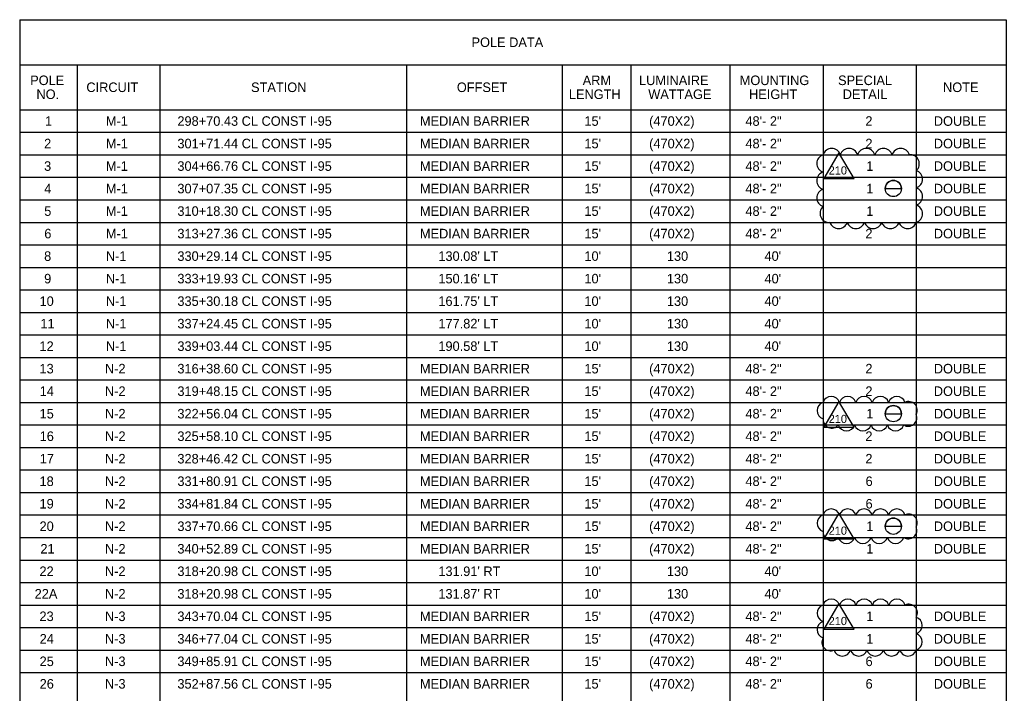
# Model space of a CAD drawing. Extents: x -816.7 to -727.6, y -2197.9 to -2187.8.
# Drawn here: x -815.95 to -808.72, y -2193.03 to -2188.1 of the extents above; entities that cross this region are included whole.
import ezdxf

# ---------------------------------------------------------------- set-up
doc = ezdxf.new("R2010")
doc.units = 0
for name, color, linetype in [('ClipBorder_dp', 7, 'Continuous'), ('MatchLines_dp', 7, 'Continuous'), ('NorthArw_dp', 7, 'Continuous'), ('PlotBorder_dp', 7, 'Continuous'), ('Scale_dp', 7, 'Continuous')]:
    doc.layers.add(name, color=color, linetype=linetype)

msp = doc.modelspace()

# ---------------------------------------------------------------- linework, layer by layer
at = {"layer": 'ClipBorder_dp'}
for p, q in [((-809.6078, -2189.3348), (-809.4893, -2189.3348)), ((-809.6078, -2189.3348), (-809.4893, -2189.3348)), ((-809.6078, -2190.9848), (-809.4893, -2190.9848)), ((-809.6078, -2190.9848), (-809.4893, -2190.9848)), ((-809.6078, -2191.8098), (-809.4893, -2191.8098)), ((-809.6078, -2191.8098), (-809.4893, -2191.8098))]:
    msp.add_line(p, q, dxfattribs=at)
for centre in [(-809.5485, -2189.3348), (-809.5485, -2190.9848), (-809.5485, -2191.8098)]:
    msp.add_circle(centre, 0.0593, dxfattribs=at)
for centre in [(-809.5485, -2189.3348), (-809.5485, -2190.9848), (-809.5485, -2191.8098)]:
    msp.add_arc(centre, 0.0593, 0, 180, dxfattribs=at)
at = {"layer": 'MatchLines_dp'}
for p, q in [((-815.9511, -2188.7573), (-808.7211, -2188.7573)), ((-815.9511, -2188.9223), (-808.7211, -2188.9223)), ((-815.9511, -2188.9223), (-808.7211, -2188.9223)), ((-815.9511, -2189.0873), (-808.7211, -2189.0873)), ((-815.9511, -2189.0873), (-808.7211, -2189.0873)), ((-815.9511, -2189.2523), (-808.7211, -2189.2523)), ((-815.9511, -2189.2523), (-808.7211, -2189.2523)), ((-815.9511, -2189.4173), (-808.7211, -2189.4173)), ((-815.9511, -2189.4173), (-808.7211, -2189.4173)), ((-815.9511, -2189.5823), (-808.7211, -2189.5823)), ((-815.9511, -2189.5823), (-808.7211, -2189.5823)), ((-815.9511, -2189.7473), (-808.7211, -2189.7473)), ((-815.9511, -2189.7473), (-808.7211, -2189.7473)), ((-815.9511, -2189.9123), (-808.7211, -2189.9123)), ((-815.9511, -2189.9123), (-808.7211, -2189.9123)), ((-815.9511, -2190.0773), (-808.7211, -2190.0773)), ((-815.9511, -2190.0773), (-808.7211, -2190.0773)), ((-815.9511, -2190.2423), (-808.7211, -2190.2423)), ((-815.9511, -2190.2423), (-808.7211, -2190.2423)), ((-815.9511, -2190.4073), (-808.7211, -2190.4073)), ((-815.9511, -2190.4073), (-808.7211, -2190.4073)), ((-815.9511, -2190.5723), (-808.7211, -2190.5723)), ((-815.9511, -2190.5723), (-808.7211, -2190.5723)), ((-815.9511, -2190.7373), (-808.7211, -2190.7373)), ((-815.9511, -2190.7373), (-808.7211, -2190.7373)), ((-815.9511, -2190.9023), (-808.7211, -2190.9023)), ((-815.9511, -2190.9023), (-808.7211, -2190.9023)), ((-815.9511, -2191.0673), (-808.7211, -2191.0673)), ((-815.9511, -2191.0673), (-808.7211, -2191.0673)), ((-815.9511, -2191.2323), (-808.7211, -2191.2323)), ((-815.9511, -2191.2323), (-808.7211, -2191.2323)), ((-815.9511, -2191.3973), (-808.7211, -2191.3973)), ((-815.9511, -2191.3973), (-808.7211, -2191.3973)), ((-815.9511, -2191.5623), (-808.7211, -2191.5623)), ((-815.9511, -2191.5623), (-808.7211, -2191.5623)), ((-815.9511, -2191.7273), (-808.7211, -2191.7273)), ((-815.9511, -2191.7273), (-808.7211, -2191.7273)), ((-815.9511, -2191.8923), (-808.7211, -2191.8923)), ((-815.9511, -2191.8923), (-808.7211, -2191.8923)), ((-815.9511, -2192.0573), (-808.7211, -2192.0573)), ((-815.9511, -2192.0573), (-808.7211, -2192.0573)), ((-815.9511, -2192.2223), (-808.7211, -2192.2223)), ((-815.9511, -2192.2223), (-808.7211, -2192.2223)), ((-815.9511, -2192.3873), (-808.7211, -2192.3873)), ((-815.9511, -2192.3873), (-808.7211, -2192.3873)), ((-815.9511, -2192.5523), (-808.7211, -2192.5523)), ((-815.9511, -2192.5523), (-808.7211, -2192.5523)), ((-815.9511, -2192.7173), (-808.7211, -2192.7173)), ((-815.9511, -2192.7173), (-808.7211, -2192.7173)), ((-815.9511, -2192.8823), (-808.7211, -2192.8823)), ((-815.9511, -2192.8823), (-808.7211, -2192.8823))]:
    msp.add_line(p, q, dxfattribs=at)
at = {"layer": 'NorthArw_dp'}
for p, q in [((-815.9511, -2188.0973), (-808.7211, -2188.0973)), ((-815.9511, -2188.0973), (-815.9511, -2194.6973)), ((-808.7211, -2188.0973), (-808.7211, -2194.6973)), ((-808.7211, -2188.0973), (-808.7211, -2194.6973)), ((-815.9511, -2188.4273), (-808.7211, -2188.4273)), ((-815.9511, -2188.4273), (-808.7211, -2188.4273))]:
    msp.add_line(p, q, dxfattribs=at)
at = {"layer": 'PlotBorder_dp'}
for points in [[(-809.9493, -2189.0739), (-810.057, -2189.2619), (-809.8364, -2189.2619)], [(-809.9493, -2190.8953), (-810.057, -2191.0833), (-809.8364, -2191.0833)], [(-809.9493, -2191.7141), (-810.057, -2191.9022), (-809.8364, -2191.9022)], [(-809.9493, -2192.3765), (-810.057, -2192.5645), (-809.8364, -2192.5645)]]:
    msp.add_lwpolyline(points, close=True, dxfattribs=at)
for centre, radius, start, end in [((-810.0436, -2189.1505), 0.0663, 107.5, 252.5), ((-810.0004, -2189.1072), 0.0663, 17.5, 162.5), ((-809.874, -2189.1072), 0.0663, 17.5, 162.5), ((-809.7475, -2189.1072), 0.0663, 17.5, 162.5), ((-809.6211, -2189.1072), 0.0663, 17.5, 162.5), ((-809.4947, -2189.1072), 0.0663, 17.5, 162.5), ((-809.4245, -2189.1531), 0.0662, 311.04336, 96.04336), ((-810.0436, -2189.2769), 0.0663, 107.5, 252.5), ((-809.401, -2189.2662), 0.0663, 287.5, 72.5), ((-810.0436, -2189.4033), 0.0663, 107.5, 252.5), ((-809.401, -2189.3926), 0.0663, 287.5, 72.5), ((-809.401, -2189.5191), 0.0663, 287.5, 72.5), ((-810.0201, -2189.5164), 0.0662, 131.04336, 276.04336), ((-809.9499, -2189.5623), 0.0663, 197.5, 342.5), ((-809.8235, -2189.5623), 0.0663, 197.5, 342.5), ((-809.6971, -2189.5623), 0.0663, 197.5, 342.5), ((-809.5707, -2189.5623), 0.0663, 197.5, 342.5), ((-809.4443, -2189.5623), 0.0663, 197.5, 342.5), ((-810.0447, -2190.9623), 0.0629, 107.5, 252.5), ((-810.0036, -2190.9212), 0.0629, 17.5, 162.5), ((-809.8835, -2190.9212), 0.0629, 17.5, 162.5), ((-809.7635, -2190.9212), 0.0629, 17.5, 162.5), ((-809.6435, -2190.9212), 0.0629, 17.5, 162.5), ((-809.5234, -2190.9212), 0.0629, 17.5, 162.5), ((-809.436, -2190.9588), 0.0629, 330.87934, 115.87934), ((-810.0009, -2191.0272), 0.0629, 175.48211, 320.48211), ((-809.4389, -2191.014), 0.0629, 237.99061, 22.99061), ((-809.8924, -2191.0483), 0.0629, 197.5, 342.5), ((-809.7723, -2191.0483), 0.0629, 197.5, 342.5), ((-809.6523, -2191.0483), 0.0629, 197.5, 342.5), ((-809.5323, -2191.0483), 0.0629, 197.5, 342.5), ((-810.0036, -2191.7462), 0.0629, 17.5, 162.5), ((-809.8835, -2191.7462), 0.0629, 17.5, 162.5), ((-809.7635, -2191.7462), 0.0629, 17.5, 162.5), ((-809.6435, -2191.7462), 0.0629, 17.5, 162.5), ((-809.5234, -2191.7462), 0.0629, 17.5, 162.5), ((-810.0447, -2191.7873), 0.0629, 107.5, 252.5), ((-809.436, -2191.7838), 0.0629, 330.87934, 115.87934), ((-809.4389, -2191.839), 0.0629, 237.99061, 22.99061), ((-810.0009, -2191.8522), 0.0629, 175.48211, 320.48211), ((-809.8924, -2191.8733), 0.0629, 197.5, 342.5), ((-809.7723, -2191.8733), 0.0629, 197.5, 342.5), ((-809.6523, -2191.8733), 0.0629, 197.5, 342.5), ((-809.5323, -2191.8733), 0.0629, 197.5, 342.5), ((-810.0034, -2192.4062), 0.0631, 17.5, 162.5), ((-809.883, -2192.4062), 0.0631, 17.5, 162.5), ((-809.7627, -2192.4062), 0.0631, 17.5, 162.5), ((-809.6423, -2192.4062), 0.0631, 17.5, 162.5), ((-809.5219, -2192.4062), 0.0631, 17.5, 162.5), ((-810.0446, -2192.4474), 0.0631, 107.5, 252.5), ((-809.4355, -2192.4446), 0.0631, 329.60153, 114.60153), ((-809.4001, -2192.5367), 0.0631, 287.5, 72.5), ((-810.0446, -2192.5678), 0.0631, 107.5, 252.5), ((-810.0092, -2192.6599), 0.0631, 149.60153, 294.60153), ((-809.4001, -2192.6571), 0.0631, 287.5, 72.5), ((-809.9227, -2192.6983), 0.0631, 197.5, 342.5), ((-809.8024, -2192.6983), 0.0631, 197.5, 342.5), ((-809.682, -2192.6983), 0.0631, 197.5, 342.5), ((-809.5616, -2192.6983), 0.0631, 197.5, 342.5), ((-809.4413, -2192.6983), 0.0631, 197.5, 342.5)]:
    msp.add_arc(centre, radius, start, end, dxfattribs=at)
at = {"layer": 'Scale_dp'}
for p, q in [((-815.5311, -2188.4273), (-815.5311, -2194.6973)), ((-815.5311, -2188.4273), (-815.5311, -2194.6973)), ((-814.9236, -2188.4273), (-814.9236, -2194.6973)), ((-814.9236, -2188.4273), (-814.9236, -2194.6973)), ((-813.1161, -2188.4273), (-813.1161, -2194.6973)), ((-813.1161, -2188.4273), (-813.1161, -2194.6973)), ((-811.9761, -2188.4273), (-811.9761, -2194.6973)), ((-811.9761, -2188.4273), (-811.9761, -2194.6973)), ((-811.4736, -2188.4273), (-811.4736, -2194.6973)), ((-811.4736, -2188.4273), (-811.4736, -2194.6973)), ((-810.7461, -2188.4273), (-810.7461, -2194.6973)), ((-810.7461, -2188.4273), (-810.7461, -2194.6973)), ((-810.0636, -2188.4273), (-810.0636, -2194.6973)), ((-810.0636, -2188.4273), (-810.0636, -2194.6973)), ((-809.3811, -2188.4273), (-809.3811, -2194.6973)), ((-815.9511, -2188.7573), (-808.7211, -2188.7573))]:
    msp.add_line(p, q, dxfattribs=at)

# ---------------------------------------------------------------- texts
at = {"layer": 'ClipBorder_dp'}
for s, p in [('POLE DATA', (-812.64, -2188.2973)), ('POLE', (-815.8744, -2188.5763)), ('ARM', (-811.8253, -2188.5763)), ('LUMINAIRE', (-811.4125, -2188.5763)), ('MOUNTING', (-810.6745, -2188.5763)), ('SPECIAL', (-809.9537, -2188.5763)), ('CIRCUIT', (-815.4627, -2188.6273)), ('STATION', (-814.2557, -2188.6273)), ('OFFSET', (-812.7476, -2188.6273)), ('NOTE', (-809.1844, -2188.6273)), ('NO.', (-815.8287, -2188.6783)), ('LENGTH', (-811.9268, -2188.6783)), ('WATTAGE', (-811.3447, -2188.6783)), ('HEIGHT', (-810.6063, -2188.6783)), ('DETAIL', (-809.9199, -2188.6783)), ('1', (-815.7658, -2188.8748)), ('M-1', (-815.3198, -2188.8748)), ('298+70.43 CL CONST I-95', (-814.7957, -2188.8748)), ('MEDIAN BARRIER', (-813.0182, -2188.8748)), ("15'", (-811.8128, -2188.8748)), ('(470X2)', (-811.3383, -2188.8748)), ('48\'- 2"', (-810.6327, -2188.8748)), ('2', (-809.7537, -2188.8748)), ('DOUBLE', (-809.2521, -2188.8748)), ('2', (-815.7725, -2189.0398)), ('M-1', (-815.3198, -2189.0398)), ('301+71.44 CL CONST I-95', (-814.7957, -2189.0398)), ('MEDIAN BARRIER', (-813.0182, -2189.0398)), ("15'", (-811.8128, -2189.0398)), ('(470X2)', (-811.3383, -2189.0398)), ('48\'- 2"', (-810.6327, -2189.0398)), ('2', (-809.7537, -2189.0398)), ('DOUBLE', (-809.2521, -2189.0398)), ('3', (-815.7725, -2189.2048)), ('M-1', (-815.3198, -2189.2048)), ('304+66.76 CL CONST I-95', (-814.7957, -2189.2048)), ('MEDIAN BARRIER', (-813.0182, -2189.2048)), ("15'", (-811.8128, -2189.2048)), ('(470X2)', (-811.3383, -2189.2048)), ('48\'- 2"', (-810.6327, -2189.2048)), ('1', (-809.747, -2189.2048)), ('DOUBLE', (-809.2521, -2189.2048)), ('4', (-815.7711, -2189.3698)), ('M-1', (-815.3198, -2189.3698)), ('307+07.35 CL CONST I-95', (-814.7957, -2189.3698)), ('MEDIAN BARRIER', (-813.0182, -2189.3698)), ("15'", (-811.8128, -2189.3698)), ('(470X2)', (-811.3383, -2189.3698)), ('48\'- 2"', (-810.6327, -2189.3698)), ('1', (-809.747, -2189.3698)), ('DOUBLE', (-809.2521, -2189.3698)), ('5', (-815.7716, -2189.5348)), ('M-1', (-815.3198, -2189.5348)), ('310+18.30 CL CONST I-95', (-814.7957, -2189.5348)), ('MEDIAN BARRIER', (-813.0182, -2189.5348)), ("15'", (-811.8128, -2189.5348)), ('(470X2)', (-811.3383, -2189.5348)), ('48\'- 2"', (-810.6327, -2189.5348)), ('1', (-809.747, -2189.5348)), ('DOUBLE', (-809.2521, -2189.5348)), ('6', (-815.7711, -2189.6998)), ('M-1', (-815.3198, -2189.6998)), ('313+27.36 CL CONST I-95', (-814.7957, -2189.6998)), ('MEDIAN BARRIER', (-813.0182, -2189.6998)), ("15'", (-811.8128, -2189.6998)), ('(470X2)', (-811.3383, -2189.6998)), ('48\'- 2"', (-810.6327, -2189.6998)), ('2', (-809.7537, -2189.6998)), ('DOUBLE', (-809.2521, -2189.6998)), ('8', (-815.7722, -2189.8648)), ('N-1', (-815.3198, -2189.8648)), ('330+29.14 CL CONST I-95', (-814.7957, -2189.8648)), ("130.08' LT", (-812.8831, -2189.8648)), ("10'", (-811.8128, -2189.8648)), ('130', (-811.2084, -2189.8648)), ("40'", (-810.4928, -2189.8648)), ('9', (-815.7721, -2190.0298)), ('N-1', (-815.3198, -2190.0298)), ('333+19.93 CL CONST I-95', (-814.7957, -2190.0298)), ("150.16' LT", (-812.8831, -2190.0298)), ("10'", (-811.8128, -2190.0298)), ('130', (-811.2084, -2190.0298)), ("40'", (-810.4928, -2190.0298)), ('10', (-815.8058, -2190.1948)), ('N-1', (-815.3198, -2190.1948)), ('335+30.18 CL CONST I-95', (-814.7957, -2190.1948)), ("161.75' LT", (-812.8831, -2190.1948)), ("10'", (-811.8128, -2190.1948)), ('130', (-811.2084, -2190.1948)), ("40'", (-810.4928, -2190.1948)), ('11', (-815.7996, -2190.3598)), ('N-1', (-815.3198, -2190.3598)), ('337+24.45 CL CONST I-95', (-814.7957, -2190.3598)), ("177.82' LT", (-812.8831, -2190.3598)), ("10'", (-811.8128, -2190.3598)), ('130', (-811.2084, -2190.3598)), ("40'", (-810.4928, -2190.3598)), ('12', (-815.8064, -2190.5248)), ('N-1', (-815.3198, -2190.5248)), ('339+03.44 CL CONST I-95', (-814.7957, -2190.5248)), ("190.58' LT", (-812.8831, -2190.5248)), ("10'", (-811.8128, -2190.5248)), ('130', (-811.2084, -2190.5248)), ("40'", (-810.4928, -2190.5248)), ('(470X2)', (-811.3383, -2190.6898)), ('13', (-815.8064, -2190.6898)), ('N-2', (-815.3265, -2190.6898)), ('316+38.60 CL CONST I-95', (-814.7957, -2190.6898)), ('MEDIAN BARRIER', (-813.0182, -2190.6898)), ("15'", (-811.8128, -2190.6898)), ('48\'- 2"', (-810.6327, -2190.6898)), ('2', (-809.7537, -2190.6898)), ('DOUBLE', (-809.2521, -2190.6898)), ('14', (-815.805, -2190.8548)), ('N-2', (-815.3265, -2190.8548)), ('319+48.15 CL CONST I-95', (-814.7957, -2190.8548)), ('MEDIAN BARRIER', (-813.0182, -2190.8548)), ("15'", (-811.8128, -2190.8548)), ('(470X2)', (-811.3383, -2190.8548)), ('48\'- 2"', (-810.6327, -2190.8548)), ('2', (-809.7537, -2190.8548)), ('DOUBLE', (-809.2521, -2190.8548)), ('15', (-815.8055, -2191.0198)), ('N-2', (-815.3265, -2191.0198)), ('322+56.04 CL CONST I-95', (-814.7957, -2191.0198)), ('MEDIAN BARRIER', (-813.0182, -2191.0198)), ("15'", (-811.8128, -2191.0198)), ('(470X2)', (-811.3383, -2191.0198)), ('48\'- 2"', (-810.6327, -2191.0198)), ('1', (-809.747, -2191.0198)), ('DOUBLE', (-809.2521, -2191.0198)), ('16', (-815.805, -2191.1848)), ('N-2', (-815.3265, -2191.1848)), ('325+58.10 CL CONST I-95', (-814.7957, -2191.1848)), ('MEDIAN BARRIER', (-813.0182, -2191.1848)), ("15'", (-811.8128, -2191.1848)), ('(470X2)', (-811.3383, -2191.1848)), ('48\'- 2"', (-810.6327, -2191.1848)), ('2', (-809.7537, -2191.1848)), ('DOUBLE', (-809.2521, -2191.1848)), ('17', (-815.8044, -2191.3498)), ('N-2', (-815.3265, -2191.3498)), ('328+46.42 CL CONST I-95', (-814.7957, -2191.3498)), ('MEDIAN BARRIER', (-813.0182, -2191.3498)), ("15'", (-811.8128, -2191.3498)), ('(470X2)', (-811.3383, -2191.3498)), ('48\'- 2"', (-810.6327, -2191.3498)), ('2', (-809.7537, -2191.3498)), ('DOUBLE', (-809.2521, -2191.3498)), ('18', (-815.8061, -2191.5148)), ('N-2', (-815.3265, -2191.5148)), ('331+80.91 CL CONST I-95', (-814.7957, -2191.5148)), ('MEDIAN BARRIER', (-813.0182, -2191.5148)), ("15'", (-811.8128, -2191.5148)), ('(470X2)', (-811.3383, -2191.5148)), ('48\'- 2"', (-810.6327, -2191.5148)), ('6', (-809.7523, -2191.5148)), ('DOUBLE', (-809.2521, -2191.5148)), ('19', (-815.806, -2191.6798)), ('N-2', (-815.3265, -2191.6798)), ('334+81.84 CL CONST I-95', (-814.7957, -2191.6798)), ('MEDIAN BARRIER', (-813.0182, -2191.6798)), ("15'", (-811.8128, -2191.6798)), ('(470X2)', (-811.3383, -2191.6798)), ('48\'- 2"', (-810.6327, -2191.6798)), ('6', (-809.7523, -2191.6798)), ('DOUBLE', (-809.2521, -2191.6798)), ('20', (-815.8058, -2191.8448)), ('N-2', (-815.3265, -2191.8448)), ('337+70.66 CL CONST I-95', (-814.7957, -2191.8448)), ('(470X2)', (-811.3383, -2191.8448)), ('48\'- 2"', (-810.6327, -2191.8448)), ('DOUBLE', (-809.2521, -2191.8448)), ('MEDIAN BARRIER', (-813.0182, -2191.8448)), ("15'", (-811.8128, -2191.8448)), ('1', (-809.747, -2191.8448)), ('21', (-815.7996, -2192.0098)), ('N-2', (-815.3265, -2192.0098)), ('340+52.89 CL CONST I-95', (-814.7957, -2192.0098)), ('MEDIAN BARRIER', (-813.0182, -2192.0098)), ("15'", (-811.8128, -2192.0098)), ('(470X2)', (-811.3383, -2192.0098)), ('48\'- 2"', (-810.6327, -2192.0098)), ('1', (-809.747, -2192.0098)), ('DOUBLE', (-809.2521, -2192.0098)), ('22', (-815.8064, -2192.1748)), ('N-2', (-815.3265, -2192.1748)), ('318+20.98 CL CONST I-95', (-814.7957, -2192.1748)), ("131.91' RT", (-812.8831, -2192.1748)), ("10'", (-811.8128, -2192.1748)), ('130', (-811.2084, -2192.1748)), ("40'", (-810.4928, -2192.1748)), ('22A', (-815.8417, -2192.3398)), ('N-2', (-815.3265, -2192.3398)), ('318+20.98 CL CONST I-95', (-814.7957, -2192.3398)), ("131.87' RT", (-812.8831, -2192.3398)), ("10'", (-811.8128, -2192.3398)), ('130', (-811.2084, -2192.3398)), ("40'", (-810.4928, -2192.3398)), ('23', (-815.8064, -2192.5048)), ('N-3', (-815.3265, -2192.5048)), ('343+70.04 CL CONST I-95', (-814.7957, -2192.5048)), ('MEDIAN BARRIER', (-813.0182, -2192.5048)), ("15'", (-811.8128, -2192.5048)), ('(470X2)', (-811.3383, -2192.5048)), ('48\'- 2"', (-810.6327, -2192.5048)), ('1', (-809.747, -2192.5048)), ('DOUBLE', (-809.2521, -2192.5048)), ('24', (-815.805, -2192.6698)), ('N-3', (-815.3265, -2192.6698)), ('346+77.04 CL CONST I-95', (-814.7957, -2192.6698)), ('MEDIAN BARRIER', (-813.0182, -2192.6698)), ("15'", (-811.8128, -2192.6698)), ('(470X2)', (-811.3383, -2192.6698)), ('48\'- 2"', (-810.6327, -2192.6698)), ('1', (-809.747, -2192.6698)), ('DOUBLE', (-809.2521, -2192.6698)), ('25', (-815.8055, -2192.8348)), ('N-3', (-815.3265, -2192.8348)), ('349+85.91 CL CONST I-95', (-814.7957, -2192.8348)), ('MEDIAN BARRIER', (-813.0182, -2192.8348)), ("15'", (-811.8128, -2192.8348)), ('(470X2)', (-811.3383, -2192.8348)), ('48\'- 2"', (-810.6327, -2192.8348)), ('6', (-809.7523, -2192.8348)), ('DOUBLE', (-809.2521, -2192.8348)), ('26', (-815.805, -2192.9998)), ('N-3', (-815.3265, -2192.9998)), ('352+87.56 CL CONST I-95', (-814.7957, -2192.9998)), ('MEDIAN BARRIER', (-813.0182, -2192.9998)), ("15'", (-811.8128, -2192.9998)), ('(470X2)', (-811.3383, -2192.9998)), ('48\'- 2"', (-810.6327, -2192.9998)), ('6', (-809.7523, -2192.9998)), ('DOUBLE', (-809.2521, -2192.9998))]:
    msp.add_text(s, height=0.07, dxfattribs=at).set_placement(p)
at = {"layer": 'PlotBorder_dp'}
for p in [(-810.0225, -2189.2318), (-810.0225, -2191.0532), (-810.0225, -2191.8721), (-810.0225, -2192.5344)]:
    msp.add_text('210', height=0.05998, rotation=0, dxfattribs=at).set_placement(p)

doc.saveas('drawing.dxf')
